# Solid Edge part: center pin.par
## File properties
Author: Robert a Rhodes jr
Template: NORMENG.PAR
Last saved by: Robert a Rhodes jr
Revision: 6
Application: Solid Edge
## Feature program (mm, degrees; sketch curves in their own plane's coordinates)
sketch for "unnamed RevolvedProtrusion 1" plane through (0, 0, 0) normal (0, -1, 0) x-axis (1, 0, 0)
  line (0, 51.4432) -> (17.145, 51.4432)
  line (17.145, 51.4432) -> (17.145, 38.7432)
  line (17.145, 38.7432) -> (12.7, 38.7432)
  line (12.7, 38.7432) -> (12.7, -24.7568)
  line (12.7, -24.7568) -> (0, -24.7568)
  line (0, -24.7568) -> (0, 51.4432)
revolve "unnamed RevolvedProtrusion 1" add finite 360 deg
sketch for "unnamed Hole 1" plane through (0, 0, 51.4432) normal (0, 0, 1) x-axis (1, 0, 0)
  hole centre (0, 0) bore radius 8.001
hole "unnamed Hole 1" through
chamfer "unnamed Chamfer 1"
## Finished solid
Body 1: solid body, 7 faces, 7 edges, 0 vertices.
  Faces by surface: cylinder 3, plane 3, cone 1
  Edges by curve: circle 7
Bounding box of the edges (mm): 34.290 x 34.290 x 76.200, from (-17.145, -17.145, -24.7568) to (17.145, 17.145, 51.4432).
Cylindrical faces by radius (mm): R8.001 x1, R12.7 x1, R17.145 x1
Conical faces (half-angle, radius in mm at the cone's reference point): 45 deg R12.7 x1
Planar faces by outward normal: +z 1, -z 2
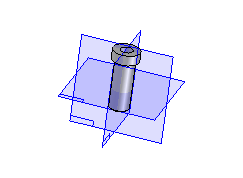
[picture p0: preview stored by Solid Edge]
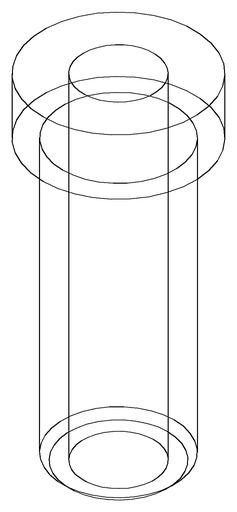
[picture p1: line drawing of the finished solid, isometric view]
